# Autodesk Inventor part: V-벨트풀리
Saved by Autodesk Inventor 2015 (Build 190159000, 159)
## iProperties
Created: 2026-07
Part Number: V-벨트풀리
Material: 일반
Document SubType Name: Modeling
Designer: user
Density: 1 g/cm^3
Appearance: 기본값
Author: user
Author: jhkim
Creation Date: 2026-07-01
Sending System: Autodesk Inventor 2027
Preprocessor: ST-DEVELOPER v20.1
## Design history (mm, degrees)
node "V-벨트풀리1"
body "Solid1"
node "기준1"
